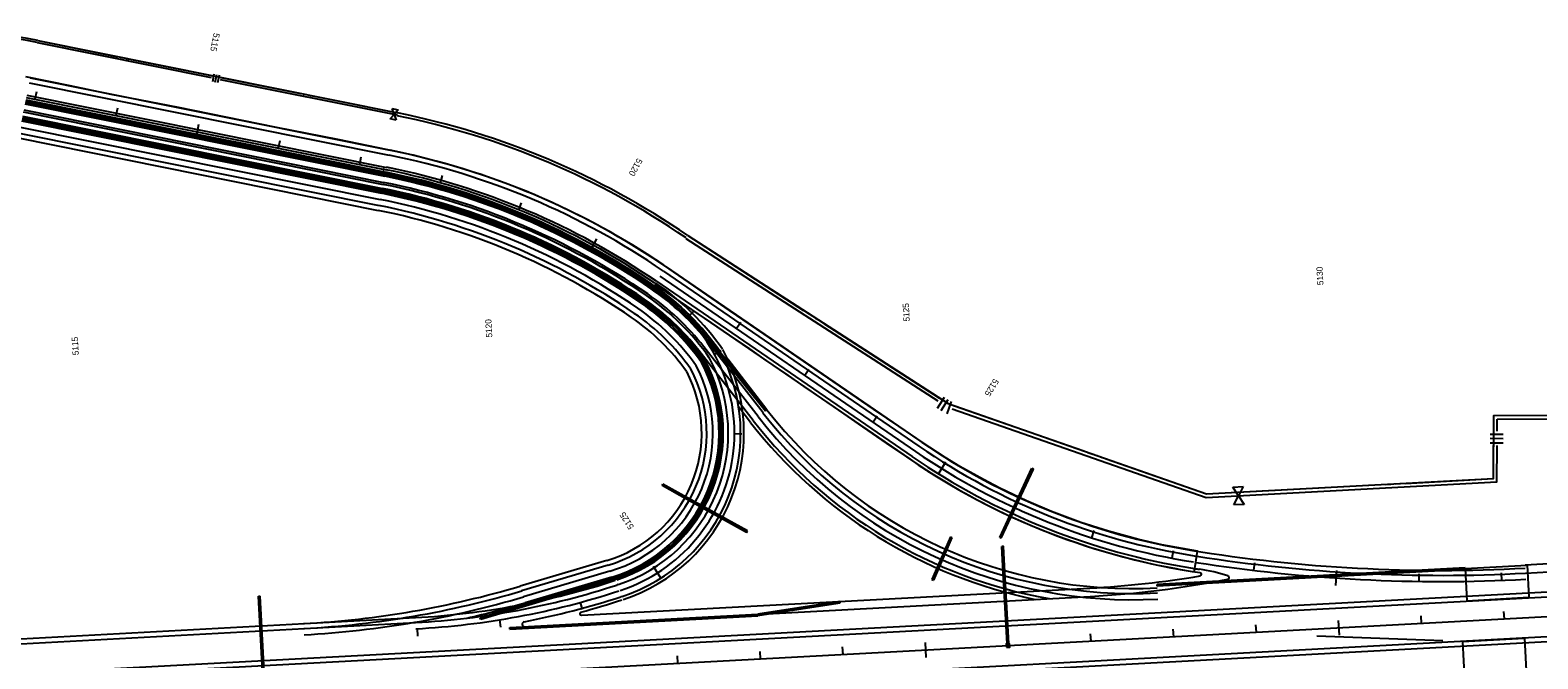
# Model space of a CAD drawing. Extents: x 192699 to 285914, y 194342 to 233219.
# Drawn here: x 262125 to 263947, y 208102 to 208861 of the extents above; entities that cross this region are included whole.
import ezdxf

# ---------------------------------------------------------------- set-up
doc = ezdxf.new("R2010")
doc.units = 0
for name, color, linetype in [('CENT LINE', 7, 'Continuous'), ('CURVE DATA', 7, 'Continuous'), ('DRAINAGE', 7, 'Continuous'), ('GUARDRAIL', 7, 'Continuous'), ('HWY 149 STAGE 2A', 7, 'Continuous'), ('R-W - CofA', 7, 'Continuous'), ('ROAD', 7, 'Continuous'), ('SHOULDER', 7, 'Continuous'), ('STATIONING1', 7, 'Continuous'), ('STATIONING2', 7, 'Continuous')]:
    doc.layers.add(name, color=color, linetype=linetype)

msp = doc.modelspace()

# ---------------------------------------------------------------- linework, layer by layer
at = {"layer": 'CENT LINE'}
for p, q in [((262120.6, 208780), (262555.5, 208692.6)), ((262886.1, 208564.1), (263194.9, 208352.4)), ((262880.2, 208555.4), (262880.2, 208555.4)), ((260415, 207963), (266337.2, 208280.3))]:
    msp.add_line(p, q, dxfattribs=at)
for centre, radius, start, end in [((262381.7, 207828.4), 881.5, 55.5667, 78.6332), ((262776.2, 208374.6), 200, 288.0667, 55.5667), ((263657.7, 209027.5), 818.5, 235.5666, 261.0666), ((263830.1, 210105.1), 1909.9, 261.0666, 273.0666), ((262540.3, 209091.7), 954.9, 273.0667, 288.0667)]:
    msp.add_arc(centre, radius, start, end, dxfattribs=at)
at = {"layer": 'DRAINAGE'}
for p, q in [((263296.8, 208248.5), (263335.4, 208332)), ((263298.6, 208247.6), (263337.3, 208331.1)), ((262990.9, 208254.6), (262910.4, 208299.1)), ((262991.9, 208256.3), (262911.4, 208300.9)), ((263305.6, 208119.9), (263300.2, 208221.7)), ((263307.6, 208120), (263302.2, 208221.8)), ((262406.9, 208071.7), (262401.3, 208177.6)), ((262408.9, 208071.8), (262403.3, 208177.7))]:
    msp.add_line(p, q, dxfattribs=at)
for points in [[(263335.4, 208332), (263337.3, 208331.1)], [(262910.4, 208299.1), (262911.4, 208300.9)], [(262990.9, 208254.6), (262991.9, 208256.3)], [(263298.6, 208247.6), (263296.8, 208248.5)], [(263300.2, 208221.7), (263302.2, 208221.8)], [(262401.3, 208177.6), (262403.3, 208177.7)]]:
    msp.add_lwpolyline(points, dxfattribs=at)
msp.add_lwpolyline([(263304.9, 208115.8), (263308.8, 208116), (263308.6, 208120), (263304.6, 208119.8)], close=True, dxfattribs=at)
at = {"layer": 'GUARDRAIL'}
msp.add_line((263832, 208123.7), (263679.9, 208129.3), dxfattribs=at)
at = {"layer": 'HWY 149 STAGE 2A'}
for p, q in [((262119.8, 208776.1), (262554.7, 208688.7)), ((262116.1, 208757.5), (262550.9, 208670)), ((262117.5, 208764.8), (262552.4, 208677.4)), ((262119, 208772.2), (262553.9, 208684.7)), ((262119.4, 208774.1), (262554.3, 208686.7)), ((262113.4, 208744.2), (262548.3, 208656.8)), ((262114.9, 208751.6), (262549.7, 208664.2)), ((262115.3, 208753.5), (262550.1, 208666.1)), ((262115.7, 208755.5), (262550.5, 208668.1)), ((262110.7, 208731), (262545.6, 208643.6)), ((262111.9, 208736.9), (262546.8, 208649.4)), ((262927.2, 208522), (262922.1, 208516.9)), ((262943.1, 208489.2), (263013.8, 208401.5)), ((262944.6, 208490.4), (263015.4, 208402.8)), ((262998.8, 208389.9), (262933.2, 208474.3)), ((263004.7, 208394.5), (262939.1, 208478.9)), ((263010.7, 208399.1), (262945, 208483.5)), ((263015.4, 208402.8), (262968, 208463.8)), ((262995.7, 208387.4), (262981.3, 208405.9)), ((263013.8, 208401.5), (263015.4, 208402.8)), ((262888.8, 208311.1), (262889.8, 208312.9)), ((262910.4, 208299.1), (262888.8, 208311.1)), ((262911.4, 208300.9), (262889.8, 208312.9)), ((263237.2, 208249.4), (263214.8, 208197.6)), ((263239, 208248.6), (263216.6, 208196.8)), ((263237.2, 208249.4), (263239, 208248.6)), ((263301.3, 208237.8), (263299.3, 208237.7)), ((263300.2, 208221.7), (263299.3, 208237.7)), ((263302.2, 208221.8), (263301.3, 208237.8)), ((262821.9, 208220.7), (262717.4, 208189.7)), ((262823.6, 208215), (262719.1, 208183.9)), ((263859, 208211.6), (263486.7, 208191.6)), ((263859, 208211.6), (263859.1, 208209.6)), ((262828.4, 208198.7), (262669.1, 208151.4)), ((262829, 208196.8), (262669.7, 208149.4)), ((262825.7, 208207.8), (262721.2, 208176.7)), ((262827.9, 208200.6), (262723.4, 208169.6)), ((263214.8, 208197.6), (263216.6, 208196.8)), ((263859.1, 208209.6), (263486.8, 208189.6)), ((263486.8, 208189.6), (263486.7, 208191.6)), ((263103.6, 208171.1), (263004.3, 208155.8)), ((263104, 208169.1), (263004.6, 208153.8)), ((263104, 208169.1), (263103.6, 208171.1)), ((262669.7, 208149.4), (262669.1, 208151.4)), ((262704.7, 208139.7), (263004.3, 208155.8)), ((262704.8, 208137.7), (262704.7, 208139.7)), ((262704.8, 208137.7), (263004.4, 208153.8))]:
    msp.add_line(p, q, dxfattribs=at)
msp.add_lwpolyline([(262122.5, 208776.5), (262135.6, 208773.9), (262149.4, 208771.1), (262167.1, 208767.6), (262177.7, 208765.4), (262192.3, 208762.5), (262204.4, 208760.1), (262223, 208756.3), (262234, 208754.1), (262250.2, 208750.9), (262263.3, 208748.2), (262284.4, 208744), (262318.5, 208737.2), (262352.8, 208730.2), (262385.3, 208723.8), (262424.9, 208715.7), (262487.1, 208703.3), (262530.7, 208694.5), (262556.3, 208689.3), (262572.1, 208685.9), (262585.4, 208682.9), (262601.1, 208679), (262615.1, 208675.3), (262626.7, 208672), (262638.1, 208668.6), (262649.3, 208665.1), (262660.4, 208661.5), (262678, 208655.4), (262690.9, 208650.7), (262713.5, 208641.8), (262737.6, 208631.5), (262757.4, 208622.4), (262771, 208615.9), (262785.2, 208608.7), (262801.5, 208600.1), (262810.7, 208595), (262821, 208589.1), (262832.6, 208582.3), (262848.9, 208572.4), (262867.5, 208560.4), (262887, 208546.9), (262902.7, 208534.6), (262911.7, 208526.8), (262922.1, 208516.9), (262927.2, 208522), (262947.9, 208507.7), (262969.9, 208492.7), (262994.2, 208476.2), (263014.2, 208462.3), (263036.9, 208446.9), (263059.9, 208431), (263081.4, 208416.2), (263108.2, 208397.8), (263125.6, 208385.9), (263159.6, 208362.5), (263184.1, 208345.8), (263210, 208328.4), (263227.9, 208317.5), (263247.2, 208305.9), (263268.7, 208294.4), (263288.2, 208284.2), (263309, 208274.3), (263325.5, 208266.9), (263348.5, 208257.1), (263374.1, 208247.6), (263388.1, 208242.6), (263406.9, 208236.3), (263433, 208228.5), (263459.5, 208221.4), (263485.7, 208215.5), (263509.8, 208210.9), (263514.6, 208209.9), (263531.6, 208207.1), (263532.4, 208211), (263535.6, 208231.8), (263492.7, 208239.4), (263464.9, 208245.9), (263428.1, 208256), (263394.8, 208266.7), (263359.1, 208280), (263329, 208292.8), (263296.7, 208308), (263277, 208318.4), (263248.6, 208334), (263225.7, 208348.2), (263200.4, 208365), (263175.1, 208382.5), (263144.3, 208403.6), (263103.3, 208431.6), (263052.1, 208466.5), (263012.2, 208494.2), (262970.3, 208522.6), (262927, 208552.4), (262890.7, 208577.4), (262870.7, 208590.6), (262853.5, 208601.4), (262833.2, 208613.4), (262810.3, 208626.1), (262792.7, 208635.5), (262777.9, 208642.7), (262755.9, 208653.1), (262724.5, 208666.6), (262699.3, 208676.3), (262677.8, 208684), (262655.7, 208691.5), (262632, 208698.7), (262609.2, 208704.8), (262588, 208710.2), (262557.6, 208716.7), (262497, 208729), (262423, 208743.7), (262304.7, 208767.8), (262223.3, 208783.6), (262173.6, 208793.8), (262119.9, 208804.7)], dxfattribs=at)
for centre, radius, start, end in [((262381.7, 207828.4), 873.5, 55.5667, 78.6332), ((262381.7, 207828.4), 875.5, 55.5667, 78.6332), ((262381.7, 207828.4), 877.5, 55.5667, 78.6332), ((262381.7, 207828.4), 856.5, 55.5667, 78.6332), ((262381.7, 207828.4), 858.5, 55.5667, 78.6332), ((262381.7, 207828.4), 866, 55.5667, 78.6332), ((262381.7, 207828.4), 837.5, 55.5667, 78.6332), ((262381.7, 207828.4), 845, 55.5667, 78.6332), ((262381.7, 207828.4), 852.5, 55.5667, 78.6332), ((262381.7, 207828.4), 854.5, 55.5667, 78.6332), ((262381.7, 207828.4), 831.5, 55.5667, 78.6332), ((262700.3, 208293.1), 302.5, 37.8798, 55.5667), ((262700.3, 208293.1), 310, 37.8798, 55.5667), ((262700.3, 208293.1), 312, 38.9237, 55.5667), ((262700.3, 208293.1), 314, 38.9237, 55.5667), ((262700.3, 208293.1), 281.5, 35.3266, 55.5667), ((262700.3, 208293.1), 289, 35.23, 55.5667), ((262700.3, 208293.1), 291, 35.2052, 55.5667), ((262700.3, 208293.1), 293, 35.1808, 55.5667), ((262700.3, 208293.1), 295, 37.8798, 55.5667), ((262700.3, 208293.1), 268, 35.5163, 55.5667), ((262700.3, 208293.1), 274, 35.4293, 55.5667), ((262776.2, 208374.6), 160.5, 286.5482, 27.5534), ((262776.2, 208374.6), 166.5, 286.5482, 27.6976), ((262776.2, 208374.6), 174, 286.5482, 27.8652), ((262776.2, 208374.6), 181.5, 286.5482, 28.0202), ((262776.2, 208374.6), 183.5, 286.5482, 28.0596), ((262776.2, 208374.6), 185.5, 286.5482, 28.0982), ((262776.2, 208374.6), 185.5, 286.5482, 25.4161), ((263457, 208746.3), 573, 217.8798, 273.0667), ((263457, 208746.3), 565.5, 217.8798, 273.0667), ((263457, 208746.3), 559.5, 217.8798, 273.0667), ((263457, 208746.3), 584.5, 217.8798, 258.4172), ((263457, 208746.3), 580.5, 217.8798, 260.0128), ((262394.9, 209275.2), 1132.4, 273.0666, 286.5482), ((262394.9, 209275.2), 1138.4, 273.0666, 286.5482), ((262394.9, 209275.2), 1145.9, 273.0666, 286.5482), ((262394.9, 209275.2), 1153.4, 282.9258, 286.5482)]:
    msp.add_arc(centre, radius, start, end, dxfattribs=at)
at = {"layer": 'R-W - CofA'}
for p, q in [((262134.4, 208848.6), (262569.2, 208761.2)), ((262347.4, 208808), (262345.5, 208798.9)), ((262350.4, 208807.4), (262348.6, 208798.2)), ((262353.5, 208806.8), (262351.7, 208797.6)), ((262560.3, 208754), (262565.2, 208759.5)), ((262565.2, 208759.5), (262562.8, 208766.5)), ((262562.8, 208766.5), (262570, 208765)), ((262570, 208765), (262565.2, 208759.5)), ((262565.2, 208759.5), (262567.5, 208752.5)), ((262567.5, 208752.5), (262560.3, 208754)), ((262919.7, 208613.2), (263234.5, 208410.1)), ((263229.7, 208417.6), (263221.1, 208404.3)), ((263234.1, 208414.8), (263225.5, 208401.5)), ((263238, 208412.8), (263232.8, 208397.8)), ((263889.2, 208373.4), (263905, 208373.3)), ((263889.2, 208368.2), (263905, 208368.1)), ((263889.2, 208362.9), (263905, 208362.8)), ((263578.2, 208309.3), (263590.6, 208309.9)), ((263585, 208298.8), (263578.2, 208309.3)), ((263590.6, 208309.9), (263585, 208298.8)), ((263579.4, 208287.8), (263585, 208298.8)), ((263591.8, 208288.4), (263579.4, 208287.8)), ((263585, 208298.8), (263591.8, 208288.4))]:
    msp.add_line(p, q, dxfattribs=at)
for points in [[(262134.4, 208848.6), (262231.1, 208829.2)], [(262133.9, 208846.2), (262344, 208803.9)], [(262234.2, 208828.6), (262237.9, 208827.8)], [(262241, 208827.2), (262244.7, 208826.4)], [(262247.8, 208825.8), (262344.5, 208806.4)], [(262355, 208801.7), (262568.8, 208758.8)], [(262355.5, 208804.2), (262452.2, 208784.7)], [(262455.3, 208784.1), (262459, 208783.4)], [(262462.1, 208782.7), (262465.9, 208782)], [(262469, 208781.4), (262569.2, 208761.2)], [(262919.7, 208613.2), (263059.8, 208522.8)], [(262917.4, 208609.6), (263221.8, 208413.3)], [(263064.3, 208519.9), (263069.7, 208516.4)], [(263074.2, 208513.5), (263079.6, 208510)], [(263084.1, 208507.1), (263224.1, 208416.8)], [(263234.5, 208410.1), (263546.6, 208301), (263893.2, 208319.6), (263893.6, 208395.7), (265244.3, 208402), (266337.2, 208427.1)], [(263239.4, 208403.9), (263546, 208296.7), (263591.2, 208299.2)], [(263240.8, 208407.9), (263398.1, 208352.9)], [(263893.5, 208376.7), (263893.6, 208395.7)], [(263893.6, 208395.7), (264062.7, 208396.5)], [(263897.8, 208391.5), (264264.5, 208393.2)], [(263897.7, 208376.7), (263897.8, 208391.5)], [(263591.2, 208299.2), (263897.4, 208315.6), (263897.6, 208359.5)], [(263786.3, 208313.8), (263893.2, 208319.6), (263893.4, 208359.7)], [(263403.1, 208351.2), (263409.2, 208349)], [(263414.3, 208347.3), (263420.3, 208345.1)], [(263425.4, 208343.4), (263546.6, 208301), (263591, 208303.4)], [(263591, 208303.4), (263757.4, 208312.3)], [(263762.7, 208312.6), (263769.2, 208312.9)], [(263774.5, 208313.2), (263780.9, 208313.6)]]:
    msp.add_lwpolyline(points, dxfattribs=at)
for centre, radius, start, end in [((262007.7, 208218.3), 643, 78.6332, 114.6332), ((262007.7, 208218.3), 640.7, 78.6332, 114.6332), ((262381.7, 207828.4), 948, 55.5667, 78.6332), ((262381.7, 207828.4), 951.5, 55.5667, 78.6332)]:
    msp.add_arc(centre, radius, start, end, dxfattribs=at)
at = {"layer": 'ROAD'}
for p, q in [((262124.1, 208797.7), (262559, 208710.2)), ((262120, 208777.1), (262554.9, 208689.6)), ((262121.2, 208782.9), (262556, 208695.5)), ((262117, 208762.4), (262551.9, 208674.9)), ((262881.9, 208557.9), (263190.7, 208346.2)), ((262890.4, 208570.3), (263199.1, 208358.6)), ((263931.9, 208205.5), (266337.2, 208334.3)), ((260415, 207993), (266337.2, 208310.3)), ((260415, 207932.9), (266337.2, 208250.2)), ((263529.5, 208211.5), (263532.4, 208211)), ((263531.8, 208226.3), (263534.7, 208225.8)), ((263859, 208211.1), (263933.9, 208215.1)), ((262723, 208140.7), (263406.1, 208177.3)), ((262835.9, 208191.6), (262834.1, 208191)), ((262840.5, 208177.3), (262838.8, 208176.8)), ((263861.1, 208172.1), (263936, 208176.2)), ((262017.1, 208114.9), (262591, 208145.7)), ((263855.8, 208122.8), (263930.7, 208126.8))]:
    msp.add_line(p, q, dxfattribs=at)
for points in [[(263859, 208211.1), (263861.1, 208172.1)], [(263933.9, 208215.1), (263936, 208176.2)], [(263855.8, 208122.8), (263858.3, 208075.9)], [(263930.7, 208126.8), (263933.2, 208079.9)]]:
    msp.add_lwpolyline(points, dxfattribs=at)
for centre, radius, start, end in [((262381.7, 207828.4), 899.5, 55.5667, 78.6332), ((262381.7, 207828.4), 878.5, 55.5667, 78.6332), ((262381.7, 207828.4), 884.5, 55.5667, 78.6332), ((262381.7, 207828.4), 863.5, 55.5667, 78.6332), ((262700.3, 208293.1), 300, 35.0977, 55.5667), ((262700.3, 208293.1), 315, 34.935, 55.5667), ((262776.2, 208374.6), 207.5, 288.0667, 28.4767), ((262776.2, 208374.6), 192.5, 288.0667, 28.2264), ((263657.7, 209027.5), 811, 235.5666, 261.0666), ((263657.7, 209027.5), 826, 235.5666, 261.0666), ((263830.1, 210105.1), 1917.4, 261.0666, 261.2359), ((263830.1, 210105.1), 1902.4, 261.0666, 273.0666), ((263342.9, 209357.6), 1182, 273.0667, 281.1836), ((263504.8, 207995.2), 217.5, 71.9078, 81.2359), ((263571.8, 208200), 2, 281.1836, 71.9078), ((262540.3, 209091.7), 947.4, 273.0667, 288.0667), ((262540.3, 209091.7), 962.4, 280.8963, 288.0667), ((262722.8, 208143.7), 3, 100.8963, 273.0667)]:
    msp.add_arc(centre, radius, start, end, dxfattribs=at)
at = {"layer": 'SHOULDER'}
for p, q in [((262125.3, 208803.5), (262560.2, 208716.1)), ((262115.9, 208756.5), (262550.7, 208669.1)), ((262893.7, 208575.2), (263202.5, 208363.5)), ((262879.6, 208554.6), (263188.4, 208342.9)), ((263931.4, 208215.5), (266336.7, 208344.3)), ((260415.3, 207987), (266337.5, 208304.3)), ((260414.7, 207938.9), (266336.9, 208256.2)), ((262791.4, 208154.4), (263405.6, 208187.3)), ((262016.8, 208120.9), (262590.7, 208151.7))]:
    msp.add_line(p, q, dxfattribs=at)
for centre, radius, start, end in [((262381.7, 207828.4), 905.5, 55.5667, 78.6332), ((262381.7, 207828.4), 857.5, 55.5667, 78.6332), ((262700.3, 208293.1), 319, 34.935, 55.5667), ((262700.3, 208293.1), 294, 35.0977, 55.5667), ((262776.2, 208374.6), 211.5, 288.0667, 28.4767), ((262776.2, 208374.6), 186.5, 288.0667, 28.2264), ((263657.7, 209027.5), 805, 235.5666, 260.6734), ((263657.7, 209027.5), 830, 235.5666, 261.7506), ((263830.1, 210105.1), 1896.4, 260.8104, 273.0666), ((262540.3, 209091.7), 941.4, 273.0667, 288.0667), ((263342.9, 209357.6), 1172, 273.0667, 279.6167), ((263538.4, 208204.1), 2, 279.6167, 81.7506), ((262791.3, 208156.4), 2, 105.0204, 273.0667), ((262540.3, 209091.7), 966.4, 285.0204, 288.0667)]:
    msp.add_arc(centre, radius, start, end, dxfattribs=at)
at = {"layer": 'STATIONING1'}
for points in [[(263905.4, 208159), (263905.9, 208150)], [(263605.8, 208142.9), (263606.3, 208134)], [(263705.7, 208148.3), (263706.7, 208130.3)], [(263805.5, 208153.6), (263806, 208144.7)], [(263206.4, 208121.5), (263207.4, 208103.6)], [(263306.3, 208126.9), (263306.7, 208117.9)], [(263406.1, 208132.2), (263406.6, 208123.3)], [(263506, 208137.6), (263506.5, 208128.6)], [(262906.8, 208105.5), (262907.3, 208096.5)], [(263006.7, 208110.8), (263007.2, 208101.9)], [(263106.5, 208116.2), (263107, 208107.2)]]:
    msp.add_lwpolyline(points, dxfattribs=at)
at = {"layer": 'STATIONING2'}
for points in [[(262132.8, 208786.7), (262131, 208777.9)], [(262132.8, 208786.7), (262131, 208777.9)], [(262230.8, 208767), (262229, 208758.2)], [(262230.8, 208767), (262229, 208758.2)], [(262328.8, 208747.3), (262325.3, 208729.7)], [(262426.9, 208727.6), (262425.1, 208718.8)], [(262426.9, 208727.6), (262425.1, 208718.8)], [(262524.9, 208707.9), (262523.1, 208699.1)], [(262524.9, 208707.9), (262523.1, 208699.1)], [(262623, 208685.5), (262620.6, 208676.9)], [(262623, 208685.5), (262620.6, 208676.9)], [(262718.5, 208652.7), (262715.1, 208644.4)], [(262718.5, 208652.7), (262715.1, 208644.4)], [(262809.7, 208609.3), (262801, 208593.5)], [(262983.7, 208508.1), (262978.6, 208500.7)], [(262960.1, 208473.8), (262952.2, 208469.5)], [(263066.2, 208451.5), (263061.1, 208444.1)], [(263148.6, 208395), (263143.6, 208387.6)], [(262985.2, 208373.4), (262976.2, 208373.5)], [(263231.3, 208339.4), (263221.8, 208324.1)], [(263410.4, 208256.7), (263407.6, 208248.1)], [(263506.2, 208232.3), (263504.5, 208223.4)], [(262888.1, 208198.1), (262878.5, 208213.3)], [(263604.5, 208217.7), (263603.4, 208208.8)], [(263703.5, 208208.5), (263702.3, 208190.5)], [(263803, 208204.5), (263802.8, 208195.5)], [(263902.5, 208205.6), (263902.8, 208196.6)], [(262792.7, 208161.4), (262790.3, 208170.1)], [(262593.7, 208129.3), (262593.2, 208138.3)], [(262694, 208140.1), (262692.6, 208149)]]:
    msp.add_lwpolyline(points, dxfattribs=at)

# ---------------------------------------------------------------- texts
at = {"layer": 'CURVE DATA'}
msp.add_text('C', height=7.5, rotation=348.6332, dxfattribs=at).set_placement((262550.5, 208689.7))
at = {"layer": 'STATIONING1'}
for s, p in [('5130', (263687.8, 208553.4)), ('5125', (263188, 208509.4)), ('5120', (262683.7, 208490.1)), ('5115', (262184.1, 208468.7))]:
    msp.add_text(s, height=7.5, rotation=93.0667, dxfattribs=at).set_placement(p)
at = {"layer": 'STATIONING2'}
for s, rotation, p in [('5115', 258.6332, (262347.2, 208858.3)), ('5120', 241.2758, (262858.9, 208707.2)), ('5125', 238.209, (263289.7, 208441)), ('5125', 122.3904, (262855.2, 208261.2))]:
    msp.add_text(s, height=7.5, rotation=rotation, dxfattribs=at).set_placement(p)

doc.saveas('drawing.dxf')
